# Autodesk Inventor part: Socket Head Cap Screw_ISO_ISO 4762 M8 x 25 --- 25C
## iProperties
Created: 2011-02
Part Number: Socket Head Cap Screw_ISO_ISO 4762 M8 x 25 --- 25C
Document SubType Name: Modeling
Designer: eric
Density: 1 g/cm^3
Author: eric
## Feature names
1. Base1
